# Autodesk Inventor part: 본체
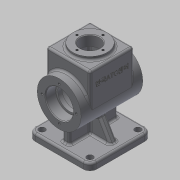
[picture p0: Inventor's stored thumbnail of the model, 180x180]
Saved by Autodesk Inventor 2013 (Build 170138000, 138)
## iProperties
Created: 2019-01
Part Number: 본체
Material: 알루미늄 6061
Document SubType Name: Modeling
Designer: mduedu
Density: 2.71 g/cm^3
Mass: 827.022 g
Surface Area: 721.983 cm^2
Volume: 305.174 cm^3
Author: mduedu
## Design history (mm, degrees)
sketch "스케치1"
  geometry: C1 r 32 at (0, 0); 1 further point
  constraints: 1 centre point, 1 coincident
  dimensions: "d0" = 64 diameter of C1
extrude "돌출1" new body sketch "스케치1" stored distance "d1" = 90; taper "d2" = 0 deg
sketch "스케치2"
  geometry: L1 (0, 32)-(50, 32); L2 (50, 32)-(50, -32); L3 (50, -32)-(0, -32); L4 (0, -32)-(0, 32); C1 r 32 at (0, 0) reference; 2 further points
  constraints: 8 end point, 2 parallel, 1 coincident, 1 horizontal, 1 midpoint, 1 perpendicular, 1 tangent
  dimensions: "d5" = 50 distance between parallel lines of L4 L2
extrude "돌출2" join sketch "스케치2" stored distance "d7" = 64; taper "d8" = 0 deg
sketch "스케치3"
  geometry: C1 r 25 at (32, 32); 1 further point
  constraints: 1 centre point, 1 coincident
  dimensions: "d9" = 50 diameter of C1
extrude "돌출3" join sketch "스케치3" distance "d10" = 5; taper "d11" = 0 deg
sketch "스케치4"
  geometry: L1 (40, 25)-(0, 25); L2 (0, 25)-(0, -25); L3 (0, -25)-(40, -25); L4 (40, -25)-(40, 25); L5 (55, -25)-(55, 25) reference; A1 r 25 centre (0, 0) between (0, 25) and (0, -25); A2 r 25 centre (0, 0) between (0, -25) and (0, 25); 2 further points
  constraints: 8 end point, 4 point on circle, 2 centre point, 2 coincident, 2 parallel, 1 horizontal, 1 midpoint, 1 perpendicular, 1 tangent
  dimensions: "d12" = 50 diameter of A1; "d13" = 15 distance between parallel lines of L4 L5
extrude "돌출4" cut sketch "스케치4" stored distance "d14" = 48; taper "d15" = 0 deg
sketch "스케치5"
  geometry: C1 r 20 at (0, 0); 1 further point
  constraints: 1 centre point, 1 coincident
  dimensions: "d16" = 40 diameter of C1
extrude "돌출5" cut sketch "스케치5" distance "d17" = 15; taper "d18" = 0 deg
sketch "스케치6"
  geometry: C1 r 17 at (0, 0); 1 further point
  constraints: 1 centre point, 1 coincident
  dimensions: "d19" = 34 diameter of C1
extrude "돌출6" cut sketch "스케치6" stored distance "d20" = 15; taper "d21" = 0 deg
fillet "모깎기1" dims "d22" = 0.3
fillet "모깎기2" dims "d23" = 3
fillet "모깎기3" dims "d24" = 3
fillet "모깎기4" dims "d25" = 3
fillet "모깎기5" dims "d26" = 3
fillet "모깎기6" dims "d27" = 3
sketch "스케치7"
  geometry: C1 r 14 at (0, 0); 1 further point
  constraints: 1 centre point, 1 coincident
  dimensions: "d28" = 28 diameter of C1
extrude "돌출7" cut sketch "스케치7" stored distance "d29" = 15; taper "d30" = 0 deg
chamfer "모따기1" distance "d31" = 1; stored, may be unused: second distance "d32" = 2, angle "d33" = 45 deg
chamfer "모따기2" distance "d34" = 1; stored, may be unused: second distance "d35" = 2, angle "d36" = 45 deg
node "작업 평면1"
sketch "스케치8"
  geometry: L1 (45, -45)-(-45, -45); L2 (-45, -45)-(-45, 45); L3 (-45, 45)-(45, 45); L4 (45, 45)-(45, -45); 3 further points
  constraints: 8 end point, 2 midpoint, 2 parallel, 1 horizontal, 1 horizontal alignment, 1 perpendicular, 1 vertical alignment
  dimensions: "d39" = 90 distance of L1.start L1.end; "d40" = 90 distance of L1.end L2.end
extrude "돌출8" join sketch "스케치8" distance "d41" = 10; taper "d42" = 0 deg
sketch "스케치9"
  geometry: L1 (-35, 5)-(35, 5); L2 (35, 5)-(35, -5); L3 (35, -5)-(-35, -5); L4 (-35, -5)-(-35, 5); 3 further points
  constraints: 8 end point, 2 midpoint, 2 parallel, 1 horizontal, 1 horizontal alignment, 1 perpendicular, 1 vertical alignment
  dimensions: "d52" = 10 distance of L1.end L2.end; "d54" = 70 distance of L1.start L1.end
extrude "돌출9" join sketch "스케치9" stored distance "d50" = 10; taper "d51" = 0 deg
sketch "스케치10"
  geometry: L1 (0, -25)-(37, -25) reference; L2 (40, -22)-(40, -14) reference; L3 (40, -14)-(54, -14) reference; L4 (54, -14)-(55, -15) reference; L5 (55, -15)-(55, -25) reference; L6 (55, -25)-(53, -25) reference; L7 (50, -28)-(50, -29) reference; L8 (47, -32)-(0, -32) reference; L9 (-31.607, -5)-(-55, -5) reference; L10 (-55, -5)-(-55, -45) reference; L11 (-55, -45)-(-65, -45) reference; L12 (-65, -45)-(-65, 45) reference; L13 (-65, 45)-(-55, 45) reference; L14 (-55, 45)-(-55, 5) reference; L15 (-55, 5)-(-31.607, 5) reference; L16 (0, 32)-(47, 32) reference; L17 (50, 29)-(50, 28) reference; L18 (53, 25)-(55, 25) reference; L19 (55, 25)-(55, 15) reference; L20 (55, 15)-(54, 14) reference; L21 (54, 14)-(40, 14) reference; L22 (40, 14)-(40, 22) reference; L23 (37, 25)-(0, 25) reference; L24 (-55, 35)-(-26.2, 18.372); A1 r 25 centre (0, 0) between (0, 25) and (0, -25) reference; A2 r 3 centre (37, -22) between (37, -25) and (40, -22) reference; A3 r 3 centre (53, -28) between (53, -25) and (50, -28) reference; A4 r 3 centre (47, -29) between (47, -32) and (50, -29) reference; A5 r 32 centre (0, 0) between (-31.607, -5) and (0, -32) reference; A6 r 32 centre (0, 0) between (0, 32) and (-31.607, 5) reference; A7 r 3 centre (47, 29) between (50, 29) and (47, 32) reference; A8 r 3 centre (53, 28) between (50, 28) and (53, 25) reference; A9 r 3 centre (37, 22) between (40, 22) and (37, 25) reference; 1 further point
  constraints: 2 end point, 1 point on circle, 1 point on line
  dimensions: "d55" = 35 vertical distance of L24.start point (0, 0); "d56" = 120 deg angle of L24 L14
feature "리브1" sketch "스케치10" dims "d57" = 1, "d58" = 10, "d59" = 0, "d60" = 0, "d61" = 1, "d62" = 1
fillet "모깎기7" dims "d63" = 3
fillet "모깎기8" dims "d64" = 3
fillet "모깎기9" dims "d65" = 10
sketch "스케치11"
  geometry: L1 (-45, 35)-(-45, -35) reference; L2 (-35, -45)-(35, -45) reference; L3 (45, -35)-(45, 35) reference; L4 (35, 45)-(-35, 45) reference; L5 (8, -29.804)-(8, -8) reference; L6 (-2, -36.732)-(2, -36.732) reference; L7 (-8, -8)-(-8, -29.804) reference; L8 (-32, -8)-(-8, -8) reference; L9 (-38, 2)-(-38, -2) reference; L10 (-8, 8)-(-32, 8) reference; L11 (-8, 29.804)-(-8, 8) reference; L12 (2, 36.732)-(-2, 36.732) reference; L13 (8, 8)-(8, 29.804) reference; L14 (32, 8)-(8, 8) reference; L15 (38, -2)-(38, 2) reference; L16 (8, -8)-(32, -8) reference; A1 r 10 centre (-35, 35) between (-35, 45) and (-45, 35) reference; A2 r 10 centre (-35, -35) between (-45, -35) and (-35, -45) reference; A3 r 10 centre (35, -35) between (35, -45) and (45, -35) reference; A4 r 10 centre (35, 35) between (45, 35) and (35, 45) reference; A5 r 6 centre (-32, -2) between (-38, -2) and (-32, -8) reference; A6 r 6 centre (-32, 2) between (-32, 8) and (-38, 2) reference; A7 r 6 centre (32, 2) between (38, 2) and (32, 8) reference; A8 r 6 centre (32, -2) between (32, -8) and (38, -2) reference; 9 further points; 4 other entities
  constraints: 4 coincident, 4 other
hole "구멍1" sketch "스케치11" at (-35, 35), (35, 35), (35, -35), (-35, -35) diameter "d66" = 9; stored, may be unused: countersink angle "d70" = 90 deg, drill point angle "d72" = 118 deg; dims "d67" = 6, "d68" = 4, "d69" = 2, "d71" = 8
fillet "모깎기10" dims "d73" = 3
sketch "스케치12"
  geometry: L1 (-3, 47)-(-3, 19.596) reference; 2 further points
  constraints: 1 other
  dimensions: "d74" = 32 distance from line of point (29, 30) L1; "d75" = 30 distance of point (29, 30) point (29, 0)
feature "엠보싱1" sketch "스케치12" dims "d76" = 0.5, "d77" = 0
sketch "스케치13"
  geometry: 4 further points
  constraints: 4 other
hole "구멍2" sketch "스케치13" at (-25, 0), (0, -25), (25, 0), (0, 25) diameter "d78" = 3.242; stored, may be unused: countersink angle "d82" = 90 deg, drill point angle "d84" = 120 deg; dims "d79" = 7, "d80" = 4, "d81" = 2, "d83" = 9
sketch "스케치14"
  geometry: 4 further points
  constraints: 4 other
hole "구멍3" sketch "스케치14" at (-25, 0), (0, -25), (25, 0), (0, 25) diameter "d85" = 3.242; stored, may be unused: countersink angle "d89" = 90 deg, drill point angle "d91" = 120 deg; dims "d86" = 7, "d87" = 4, "d88" = 2, "d90" = 9
sketch "스케치15"
  geometry: 4 further points
  constraints: 4 other
hole "구멍4" sketch "스케치15" at (0, -19), (19, 0), (0, 19), (-19, 0) diameter "d92" = 3.242; stored, may be unused: countersink angle "d96" = 90 deg, drill point angle "d98" = 120 deg; dims "d93" = 8, "d94" = 4, "d95" = 2, "d97" = 10
node "솔리드1"
mirror "대칭1"
mirror "대칭2"
node "투영된 루프1"
node "절단 모서리 투영1"
node "절단 모서리 투영2"
other parameters: "d37" = -65
